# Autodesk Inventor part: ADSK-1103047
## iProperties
Shininess: 54.0
Length Units: 11269
Angle Units: 11279
Time Units: 11290
Mass Units: 11286
Length Display Precision: 2
Angle Display Precision: 2
Compacted: True
Created: 2000-07
Part Number: ADSK-1103047
Document SubType Name: Modeling
Description: ENGINE SLEEVE - REAR
Mass: 20.4004 g
Surface Area: 29.8059 cm^2
Volume: 2.59878 cm^3
Density: 7.85 g/cm^3
Material: Cast Steel
Density: 0.0
Volumn: 0.0
Area: 0.0
PropertySet Name: Model Information
Control State: 0
Master: False
Checked Out: False
Author: Autodesk, Inc.
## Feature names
1. Extrusion3
2. Fillet1
3. Revolution1
4. Fillet2
5. Sweep1
6. Fillet3
7. Fillet4
8. Mirror1
